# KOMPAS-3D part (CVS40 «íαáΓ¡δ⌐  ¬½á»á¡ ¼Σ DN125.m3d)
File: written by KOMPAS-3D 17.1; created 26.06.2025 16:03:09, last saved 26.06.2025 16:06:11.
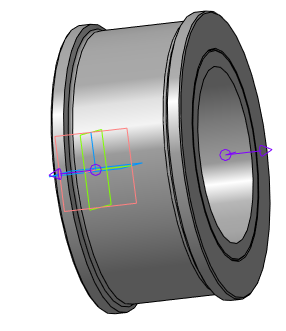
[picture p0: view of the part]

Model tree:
1. Эскиз:1
2. Элемент вращения:1
     Угол 1 = 360
3. Присоединительная точка:1
4. Присоединительная точка:2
